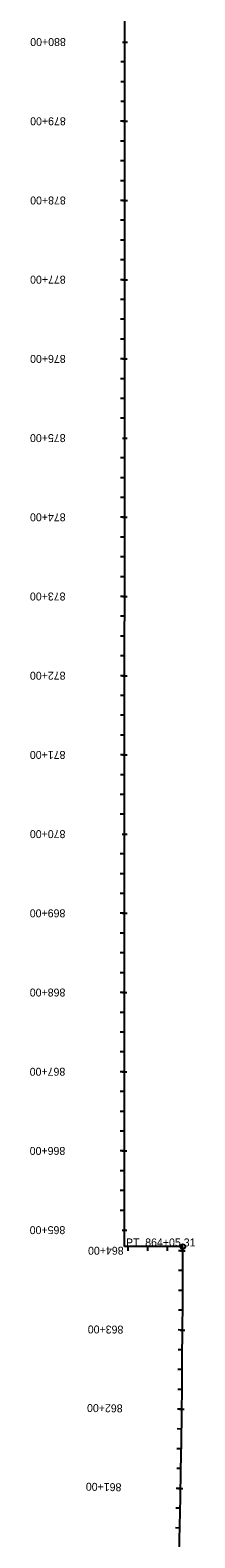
# Model space of a CAD drawing. Extents: x 18543252 to 18543633, y 7433057 to 7440612.
# Drawn here: x 18543266 to 18543475, y 7436828 to 7438732 of the extents above; entities that cross this region are included whole.
import ezdxf

# ---------------------------------------------------------------- set-up
doc = ezdxf.new("R2010")
doc.units = 0
for name, color, linetype in [('PS_BOLT', 7, 'Continuous'), ('PS_DIM', 7, 'Continuous'), ('PS_MID', 7, 'Continuous'), ('PS_SHAPE', 7, 'Continuous')]:
    doc.layers.add(name, color=color, linetype=linetype)

msp = doc.modelspace()

# ---------------------------------------------------------------- linework, layer by layer
at = {"layer": 'PS_BOLT'}
for p, q in [((18543383.7, 7438716.8), (18543389.8, 7438716.8)), ((18543386.7, 7438616.8), (18543381.2, 7438616.8)), ((18543386.7, 7438516.8), (18543381.2, 7438516.8)), ((18543386.6, 7438416.8), (18543381.2, 7438416.8)), ((18543386.6, 7438316.8), (18543381.1, 7438316.8)), ((18543383.5, 7438216.8), (18543389.6, 7438216.8)), ((18543386.5, 7438116.8), (18543381, 7438116.8)), ((18543386.4, 7438016.8), (18543381, 7438016.8)), ((18543386.4, 7437916.8), (18543380.9, 7437916.8)), ((18543386.3, 7437816.8), (18543380.9, 7437816.8)), ((18543383.2, 7437716.8), (18543389.3, 7437716.8)), ((18543386.2, 7437616.8), (18543380.8, 7437616.8)), ((18543386.2, 7437516.8), (18543380.7, 7437516.8)), ((18543386.1, 7437416.8), (18543380.7, 7437416.8)), ((18543386.1, 7437316.8), (18543380.6, 7437316.8)), ((18543383, 7437216.8), (18543389.1, 7437216.8)), ((18543460, 7437190.7), (18543454.6, 7437190.7)), ((18543459.7, 7437090.7), (18543454.2, 7437090.8)), ((18543458.7, 7436990.7), (18543453.3, 7436990.8)), ((18543457.2, 7436890.7), (18543451.7, 7436890.8))]:
    msp.add_line(p, q, dxfattribs=at)
at = {"layer": 'PS_DIM'}
msp.add_line((18543460, 7437196), (18543388, 7437196.1), dxfattribs=at)
msp.add_circle((18543460, 7437196), 3.12, dxfattribs=at)
at = {"layer": 'PS_MID'}
for p, q in [((18543383.7, 7438716.8), (18543389.8, 7438716.8)), ((18543386.7, 7438691.8), (18543381.3, 7438691.8)), ((18543386.7, 7438666.8), (18543381.3, 7438666.8)), ((18543386.7, 7438641.8), (18543381.3, 7438641.8)), ((18543383.6, 7438616.8), (18543389.8, 7438616.8)), ((18543386.7, 7438591.8), (18543381.2, 7438591.8)), ((18543386.7, 7438566.8), (18543381.2, 7438566.8)), ((18543386.7, 7438541.8), (18543381.2, 7438541.8)), ((18543383.6, 7438516.8), (18543389.7, 7438516.8)), ((18543386.6, 7438491.8), (18543381.2, 7438491.8)), ((18543386.6, 7438466.8), (18543381.2, 7438466.8)), ((18543386.6, 7438441.8), (18543381.2, 7438441.8)), ((18543383.6, 7438416.8), (18543389.7, 7438416.8)), ((18543386.6, 7438391.8), (18543381.1, 7438391.8)), ((18543386.6, 7438366.8), (18543381.1, 7438366.8)), ((18543386.6, 7438341.8), (18543381.1, 7438341.8)), ((18543383.5, 7438316.8), (18543389.6, 7438316.8)), ((18543386.6, 7438291.8), (18543381.1, 7438291.8)), ((18543386.5, 7438266.8), (18543381.1, 7438266.8)), ((18543386.5, 7438241.8), (18543381.1, 7438241.8)), ((18543383.5, 7438216.8), (18543389.6, 7438216.8)), ((18543386.5, 7438191.8), (18543381, 7438191.8)), ((18543386.5, 7438166.8), (18543381, 7438166.8)), ((18543386.5, 7438141.8), (18543381, 7438141.8)), ((18543383.4, 7438116.8), (18543389.5, 7438116.8)), ((18543386.5, 7438091.8), (18543381, 7438091.8)), ((18543386.4, 7438066.8), (18543381, 7438066.8)), ((18543386.4, 7438041.8), (18543381, 7438041.8)), ((18543383.4, 7438016.8), (18543389.5, 7438016.8)), ((18543386.4, 7437991.8), (18543381, 7437991.8)), ((18543386.4, 7437966.8), (18543380.9, 7437966.8)), ((18543386.4, 7437941.8), (18543380.9, 7437941.8)), ((18543383.3, 7437916.8), (18543389.4, 7437916.8)), ((18543386.4, 7437891.8), (18543380.9, 7437891.8)), ((18543386.4, 7437866.8), (18543380.9, 7437866.8)), ((18543386.3, 7437841.8), (18543380.9, 7437841.8)), ((18543383.3, 7437816.8), (18543389.4, 7437816.8)), ((18543386.3, 7437791.8), (18543380.9, 7437791.8)), ((18543386.3, 7437766.8), (18543380.8, 7437766.8)), ((18543386.3, 7437741.8), (18543380.8, 7437741.8)), ((18543383.2, 7437716.8), (18543389.3, 7437716.8)), ((18543386.3, 7437691.8), (18543380.8, 7437691.8)), ((18543386.3, 7437666.8), (18543380.8, 7437666.8)), ((18543386.2, 7437641.8), (18543380.8, 7437641.8)), ((18543383.2, 7437616.8), (18543389.3, 7437616.8)), ((18543386.2, 7437591.8), (18543380.8, 7437591.8)), ((18543386.2, 7437566.8), (18543380.8, 7437566.8)), ((18543386.2, 7437541.8), (18543380.7, 7437541.8)), ((18543383.1, 7437516.8), (18543389.2, 7437516.8)), ((18543386.2, 7437491.8), (18543380.7, 7437491.8)), ((18543386.2, 7437466.8), (18543380.7, 7437466.8)), ((18543386.2, 7437441.8), (18543380.7, 7437441.8)), ((18543383.1, 7437416.8), (18543389.2, 7437416.8)), ((18543386.1, 7437391.8), (18543380.7, 7437391.8)), ((18543386.1, 7437366.8), (18543380.7, 7437366.8)), ((18543386.1, 7437341.8), (18543380.6, 7437341.8)), ((18543383, 7437316.8), (18543389.2, 7437316.8)), ((18543386.1, 7437291.8), (18543380.6, 7437291.8)), ((18543386.1, 7437266.8), (18543380.6, 7437266.8)), ((18543386.1, 7437241.8), (18543380.6, 7437241.8)), ((18543383, 7437216.8), (18543389.1, 7437216.8)), ((18543390.3, 7437196.1), (18543390.3, 7437190.6)), ((18543415.3, 7437196.1), (18543415.3, 7437190.6)), ((18543440.3, 7437196), (18543440.3, 7437190.6)), ((18543457, 7437190.7), (18543463.1, 7437190.7)), ((18543460, 7437165.7), (18543454.5, 7437165.7)), ((18543459.9, 7437140.7), (18543454.5, 7437140.7)), ((18543459.8, 7437115.7), (18543454.4, 7437115.8)), ((18543456.6, 7437090.7), (18543462.7, 7437090.7)), ((18543459.5, 7437065.7), (18543454, 7437065.8)), ((18543459.3, 7437040.7), (18543453.8, 7437040.8)), ((18543459, 7437015.7), (18543453.5, 7437015.8)), ((18543455.7, 7436990.8), (18543461.8, 7436990.7)), ((18543458.4, 7436965.7), (18543452.9, 7436965.8)), ((18543458, 7436940.7), (18543452.6, 7436940.8)), ((18543457.6, 7436915.7), (18543452.2, 7436915.8)), ((18543454.1, 7436890.8), (18543460.2, 7436890.7)), ((18543456.7, 7436865.7), (18543451.2, 7436865.9)), ((18543456.2, 7436840.7), (18543450.7, 7436840.9))]:
    msp.add_line(p, q, dxfattribs=at)
at = {"layer": 'PS_SHAPE'}
for p, q in [((18543386, 7437196.1), (18543387.6, 7440601.5)), ((18543460, 7437196), (18543386, 7437196.1))]:
    msp.add_line(p, q, dxfattribs=at)
msp.add_arc((18526279.5, 7437204.1), 17180.5, 356.21104, 359.97302, dxfattribs=at)

# ---------------------------------------------------------------- texts
at = {"layer": 'PS_BOLT'}
for s, p in [('880+00', (18543311.8, 7438721.8)), ('875+00', (18543311.5, 7438221.8)), ('870+00', (18543311.3, 7437721.8)), ('865+00', (18543311.1, 7437221.8))]:
    msp.add_text(s, height=10.02, rotation=179.973, dxfattribs=at).set_placement(p)
at = {"layer": 'PS_DIM'}
for s, p in [('PT', (18543388, 7437196.3)), ('864+05.31', (18543412.3, 7437196.3))]:
    msp.add_text(s, height=10.02, rotation=359.973, dxfattribs=at).set_placement(p)
at = {"layer": 'PS_MID'}
for s, rotation, p in [('880+00', 179.973, (18543311.8, 7438721.8)), ('879+00', 179.973, (18543311.7, 7438621.8)), ('878+00', 179.973, (18543311.7, 7438521.8)), ('877+00', 179.973, (18543311.6, 7438421.8)), ('876+00', 179.973, (18543311.6, 7438321.8)), ('875+00', 179.973, (18543311.5, 7438221.8)), ('874+00', 179.973, (18543311.5, 7438121.8)), ('873+00', 179.973, (18543311.4, 7438021.8)), ('872+00', 179.973, (18543311.4, 7437921.8)), ('871+00', 179.973, (18543311.3, 7437821.8)), ('870+00', 179.973, (18543311.3, 7437721.8)), ('869+00', 179.973, (18543311.2, 7437621.8)), ('868+00', 179.973, (18543311.2, 7437521.8)), ('867+00', 179.973, (18543311.1, 7437421.8)), ('866+00', 179.973, (18543311.1, 7437321.8)), ('865+00', 179.973, (18543311.1, 7437221.8)), ('864+00', 179.9553, (18543385, 7437195.8)), ('863+00', 179.6218, (18543384.7, 7437096.2)), ('862+00', 179.2883, (18543383.8, 7436996.7)), ('861+00', 178.9548, (18543382.3, 7436897.1))]:
    msp.add_text(s, height=10.02, rotation=rotation, dxfattribs=at).set_placement(p)

doc.saveas('drawing.dxf')
